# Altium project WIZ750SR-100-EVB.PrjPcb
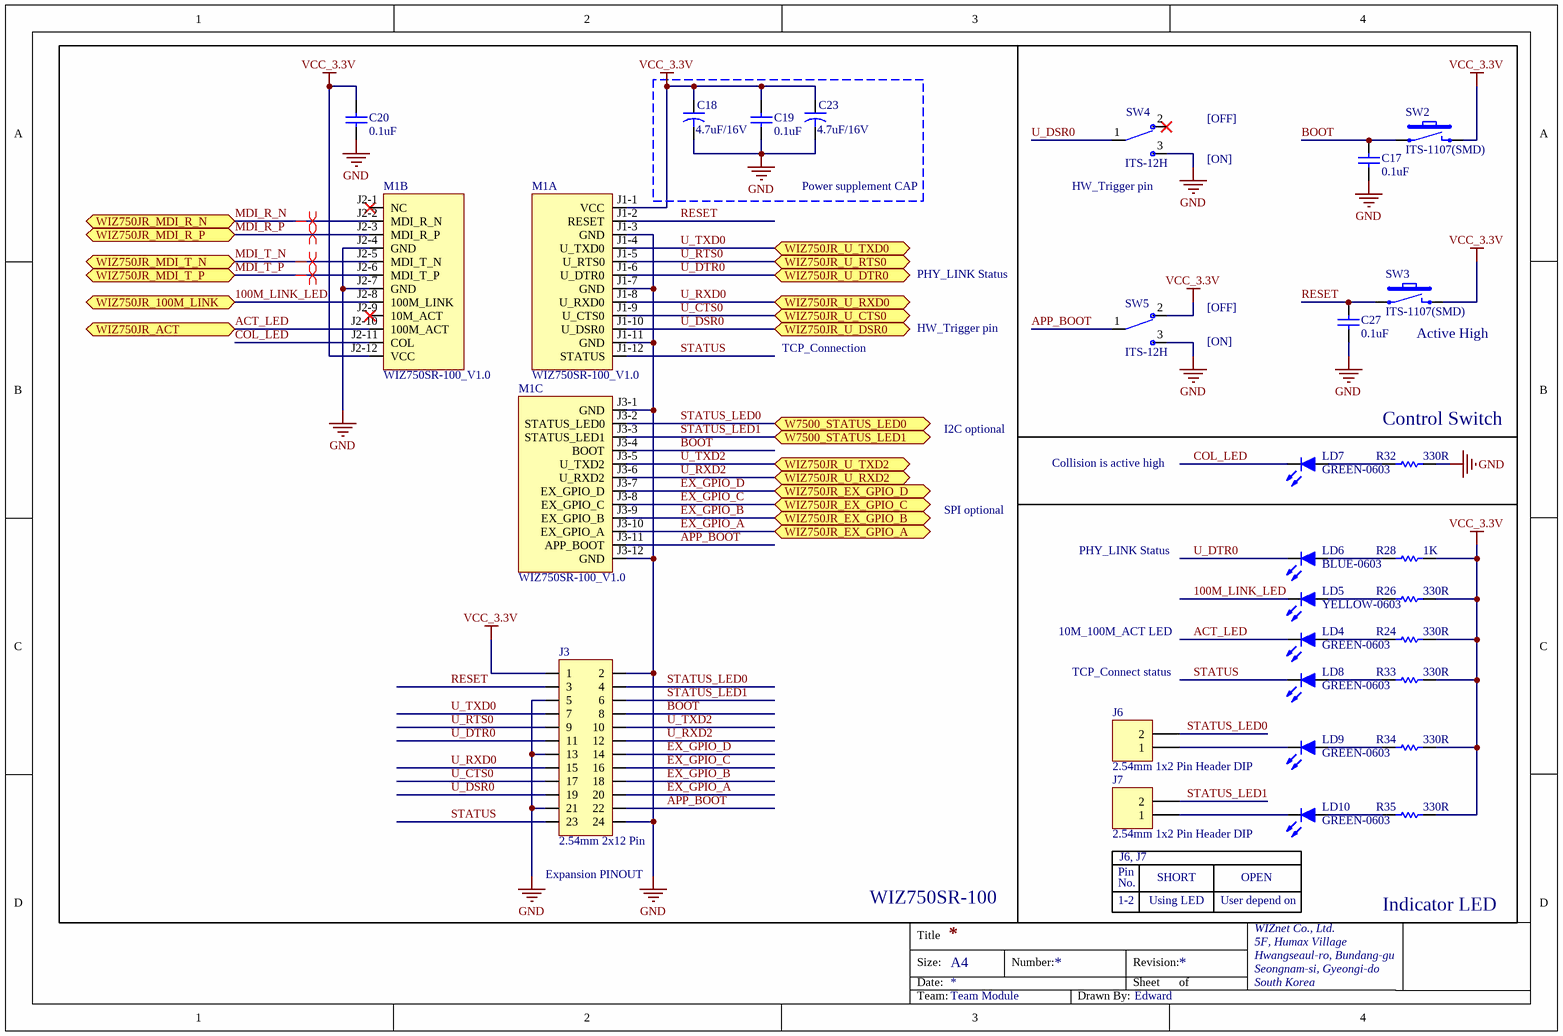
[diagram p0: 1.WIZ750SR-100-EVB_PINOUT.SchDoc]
4 sheets, 94 parts. Net scope: flat (ports and power ports of the same name join across sheets).
Board file: WIZ750SR-100-EVB.PcbDoc
Sheets:
  1.WIZ750SR-100-EVB_PINOUT.SchDoc
  2.WIZ750SR-100-EVB_PWR.SchDoc
  3.WIZ750SR-100-EVB_Data.SchDoc
  4.WIZ750SR-100-EVB_GPIO.SchDoc

## Sheet 1.WIZ750SR-100-EVB_PINOUT.SchDoc
size A4; Team: Wiki

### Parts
C17  0.1uF  [CAP-0603]
C18  4.7uF/16V  [CAP-A Size]
C19  0.1uF  [CAP-0603]
C20  0.1uF  [CAP-0603]
C23  4.7uF/16V  [CAP-A Size]
C27  0.1uF  [CAP-0603]
J3  2.54mm 2x12 Pin  [IDC-2x12_socket_2.54mm]
J6  2.54mm 1x2 Pin Header DIP  [IDC-1X2]
J7  2.54mm 1x2 Pin Header DIP  [IDC-1X2]
LD4  GREEN-0603  [LED-0603-GREEN]
LD5  YELLOW-0603  [LED-0603-YELLOW]
LD6  BLUE-0603  [LED-0603-GREEN]
LD7  GREEN-0603  [LED-0603-GREEN]
LD8  GREEN-0603  [LED-0603-GREEN]
LD9  GREEN-0603  [LED-0603-GREEN]
LD10  GREEN-0603  [LED-0603-GREEN]
M1  WIZ750SR-100_V1.0  [WIZ750JR_V1.0]  (parts A,B,C of 3)
R24  330R  [RES-0603]
R26  330R  [RES-0603]
R28  1K  [RES-0603]
R32  330R  [RES-0603]
R33  330R  [RES-0603]
R34  330R  [RES-0603]
R35  330R  [RES-0603]
SW2  ITS-1107(SMD)  [ITS-1107(SMD)]
SW3  ITS-1107(SMD)  [ITS-1107(SMD)]
SW4  ITS-12H  [ITS-12H]
SW5  ITS-12H  [ITS-12H]

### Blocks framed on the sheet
Power supplement CAP: C18 C19 C23

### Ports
W7500_STATUS_LED0, W7500_STATUS_LED1, WIZ750JR_100M_LINK, WIZ750JR_ACT, WIZ750JR_EX_GPIO_A, WIZ750JR_EX_GPIO_B, WIZ750JR_EX_GPIO_C, WIZ750JR_EX_GPIO_D, WIZ750JR_MDI_R_N, WIZ750JR_MDI_R_P, WIZ750JR_MDI_T_N, WIZ750JR_MDI_T_P, WIZ750JR_U_CTS0, WIZ750JR_U_DSR0, WIZ750JR_U_DTR0, WIZ750JR_U_RTS0, WIZ750JR_U_RXD0, WIZ750JR_U_RXD2, WIZ750JR_U_TXD0, WIZ750JR_U_TXD2

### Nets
GND: C17.1 C18.2 C19.1 C20.1 C23.2 C27.1 J3.2 J3.5 J3.13 J3.21 J3.24 M1.J1-3(GND) M1.J1-7(GND) M1.J1-11(GND) M1.J2-4(GND) M1.J2-7(GND) M1.J3-1(GND) M1.J3-12(GND) R32.2 SW4.3 SW5.3
VCC_3.3V: C18.1 C19.2 C20.2 C23.1 J3.1 M1.J1-1(VCC) M1.J2-12(VCC) R24.2 R26.2 R28.2 R33.2 R34.2 R35.2 SW2.2 SW3.2 SW5.2
100M_LINK_LED: LD5.2(K) M1.J2-8(100M_LINK) ; port WIZ750JR_100M_LINK
ACT_LED: LD4.2(K) M1.J2-10(100M_ACT) ; port WIZ750JR_ACT
APP_BOOT: J3.22 M1.J3-11(APP_BOOT) SW5.1
BOOT: C17.2 J3.8 M1.J3-4(BOOT) SW2.1
COL_LED: LD7.2(K) M1.J2-11(COL)
EX_GPIO_A: J3.20 M1.J3-10(EX_GPIO_A) ; port WIZ750JR_EX_GPIO_A
EX_GPIO_B: J3.18 M1.J3-9(EX_GPIO_B) ; port WIZ750JR_EX_GPIO_B
EX_GPIO_C: J3.16 M1.J3-8(EX_GPIO_C) ; port WIZ750JR_EX_GPIO_C
EX_GPIO_D: J3.14 M1.J3-7(EX_GPIO_D) ; port WIZ750JR_EX_GPIO_D
MDI_R_N: M1.J2-2(MDI_R_N) ; port WIZ750JR_MDI_R_N
MDI_R_P: M1.J2-3(MDI_R_P) ; port WIZ750JR_MDI_R_P
MDI_T_N: M1.J2-5(MDI_T_N) ; port WIZ750JR_MDI_T_N
MDI_T_P: M1.J2-6(MDI_T_P) ; port WIZ750JR_MDI_T_P
RESET: C27.2 J3.3 M1.J1-2(RESET) SW3.1
STATUS: J3.23 LD8.2(K) M1.J1-12(STATUS)
STATUS_LED0: J3.4 J6.2 M1.J3-2(STATUS_LED0) ; port W7500_STATUS_LED0
STATUS_LED1: J3.6 J7.2 M1.J3-3(STATUS_LED1) ; port W7500_STATUS_LED1
U_CTS0: J3.17 M1.J1-9(U_CTS0) ; port WIZ750JR_U_CTS0
U_DSR0: J3.19 M1.J1-10(U_DSR0) SW4.1 ; port WIZ750JR_U_DSR0
U_DTR0: J3.11 LD6.2(K) M1.J1-6(U_DTR0) ; port WIZ750JR_U_DTR0
U_RTS0: J3.9 M1.J1-5(U_RTS0) ; port WIZ750JR_U_RTS0
U_RXD0: J3.15 M1.J1-8(U_RXD0) ; port WIZ750JR_U_RXD0
U_RXD2: J3.12 M1.J3-6(U_RXD2) ; port WIZ750JR_U_RXD2
U_TXD0: J3.7 M1.J1-4(U_TXD0) ; port WIZ750JR_U_TXD0
U_TXD2: J3.10 M1.J3-5(U_TXD2) ; port WIZ750JR_U_TXD2
NetJ6_1: J6.1 LD9.2(K)
NetJ7_1: J7.1 LD10.2(K)
NetLD4_1: LD4.1(A) R24.1
NetLD5_1: LD5.1(A) R26.1
NetLD6_1: LD6.1(A) R28.1
NetLD7_1: LD7.1(A) R32.1
NetLD8_1: LD8.1(A) R33.1
NetLD9_1: LD9.1(A) R34.1
NetLD10_1: LD10.1(A) R35.1

Not connected (* = marked no-connect by the designer): M1 J2-1(NC)* J2-9(10M_ACT)*; SW4 2*

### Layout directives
differential pair: MDI_R_N, MDI_R_P, MDI_T_N, MDI_T_P

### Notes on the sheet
- [ON]
- [OFF]
- (near SW4) HW_Trigger pin
- PHY_LINK Status
- TCP_Connection
- HW_Trigger pin
- (near SW3) Active High
- I2C optional
- (near R32) Control Switch
- SPI optional
- Collision is active high
- 10M_100M_ACT LED
- TCP_Connect status
- (near J3) Expansion PINOUT
- WIZ750SR-100
- Pin
- 1-2
- No.
- (near J7) J6, J7
- Using LED
- SHORT
- User depend on
- OPEN
- Indicator LED

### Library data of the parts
C17 C19 C20 C27 = CAP-0603: Ceramic CAP 0603(1608)
C18 C23 = CAP-A Size: Tantla CAP A Size EIA/IECQ 3216
J3 = Header 2x12: pin header 2.54mm 2x12
J6 J7 = Header 1x2: pin header 2.54mm 1x2
LD4-LD10 = LED-0603
M1 = WIZ750JR_V0.2: Serial to ethernet module, 50mmx30mm, 7500 + External PHY
R24 R26 R28 R32-R35 = RES-0603
SW2 SW3 = ITS-1107(SMD): TACT SW, SMD
SW4 SW5 = ITS-12H: Slide Switch

## Sheet 2.WIZ750SR-100-EVB_PWR.SchDoc
size A4; Team: Wiki
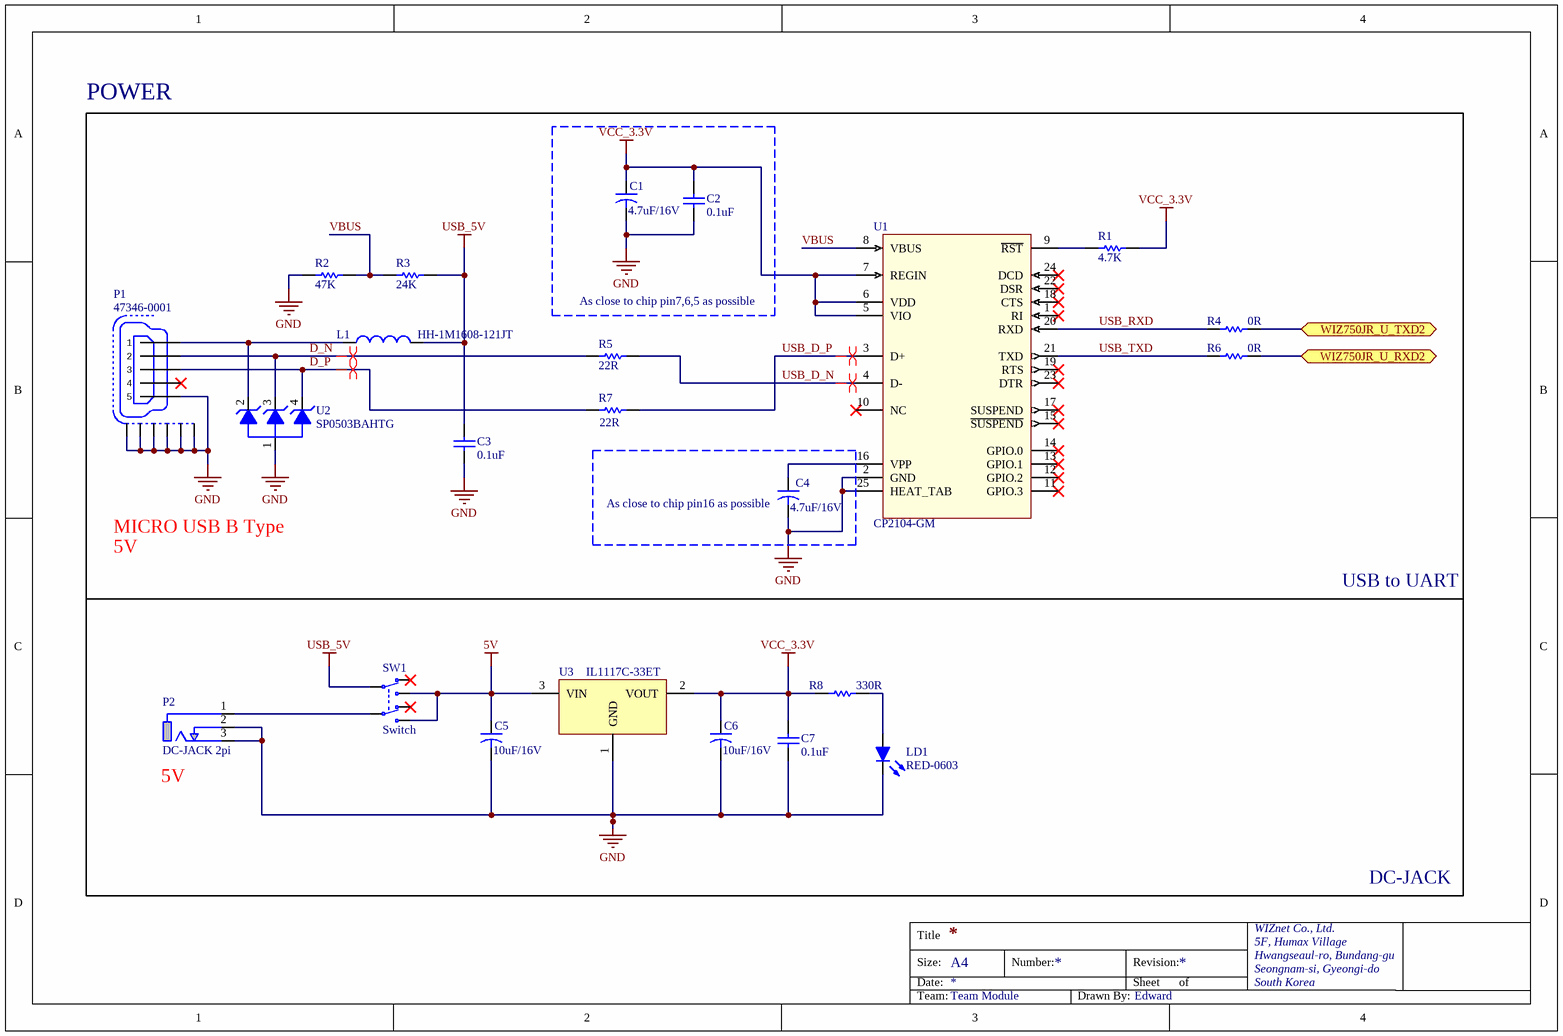
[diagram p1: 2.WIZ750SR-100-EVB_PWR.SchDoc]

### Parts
C1  4.7uF/16V  [CAP-A Size]
C2  0.1uF  [CAP-0603]
C3  0.1uF  [CAP-0603]
C4  4.7uF/16V  [CAP-A Size]
C5  10uF/16V  [CAP-A Size]
C6  10uF/16V  [CAP-A Size]
C7  0.1uF  [CAP-0603]
L1  HH-1M1608-121JT  [IND-0603]
LD1  RED-0603  [LED-0603-RED]
P1  47346-0001  [USB-MICRO-B(SMD)]
P2  DC-JACK 2pi  [DC-JACK 2pi]
R1  4.7K  [RES-0603]
R2  47K  [RES-0603]
R3  24K  [RES-0603]
R4  0R  [RES-0603]
R5  22R  [RES-0603]
R6  0R  [RES-0603]
R7  22R  [RES-0603]
R8  330R  [RES-0603]
SW1  Switch  [JS202011SCQN]
U1  CP2104-GM  [CP2104_QFN24_PAD]
U2  SP0503BAHTG  [SP0503BAHTG]
U3  IL1117C-33ET  [IL1117C-33ET]

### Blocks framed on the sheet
POWER: C3 C5-C7 L1 LD1 P1 P2 R1-R8 SW1 U1-U3
As close to chip pin7,6,5 as possible: C1 C2
As close to chip pin16 as possible: C4

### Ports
WIZ750JR_U_RXD2, WIZ750JR_U_TXD2

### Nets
5V: C5.1 SW1.1(N.O-1) SW1.4(N.O-2) U3.3(VIN)
GND: C1.2 C2.1 C3.1 C4.2 C5.2 C6.2 C7.1 LD1.2(K) P1.5 P1.6 P1.7 P1.8 P1.9 P1.10 P1.11 P2.2(GND) P2.3(GND) R2.1 U1.2(GND) U1.25(HEAT_TAB) U2.1 U3.1(GND)
USB_5V: C3.2 L1.2 R3.2 SW1.2(COM-1)
VCC_3.3V: C1.1 C2.2 C6.1 C7.2 R1.2 R8.1 U1.5(VIO) U1.6(VDD) U1.7(REGIN) U3.2(VOUT)
D_N: P1.2 R5.1 U2.3
D_P: P1.3 R7.1 U2.4
U_RXD2: R6.2 ; port WIZ750JR_U_RXD2
U_TXD2: R4.2 ; port WIZ750JR_U_TXD2
USB_D_N: R5.2 U1.4(D-)
USB_D_P: R7.2 U1.3(D+)
USB_RXD: R4.1 U1.20(RXD)
USB_TXD: R6.1 U1.21(TXD)
VBUS: R2.2 R3.1 U1.8(VBUS)
NetC4_1: C4.1 U1.16(VPP)
NetL1_1: L1.1 P1.1 U2.2
NetLD1_1: LD1.1(A) R8.2
NetP2_1: P2.1(VCC) SW1.5(COM-2)
NetR1_1: R1.1 U1.9(~{RST})

Not connected (* = marked no-connect by the designer): P1 4*; SW1 3(N.C-1)* 6(N.C-2)*; U1 1(RI)* 10(NC)* 11(GPIO.3)* 12(GPIO.2)* 13(GPIO.1)* 14(GPIO.0)* 15(~{SUSPEND})* 17(SUSPEND)* 18(CTS)* 19(RTS)* 22(DSR)* 23(DTR)* 24(DCD)*

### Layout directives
differential pair: D_N, D_P, USB_D_N, USB_D_P

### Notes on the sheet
- MICRO USB B Type
- 5V
- USB to UART
- (near P2) 5V
- DC-JACK

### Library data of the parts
C1 C4-C6 = CAP-A Size: Tantla CAP A Size EIA/IECQ 3216
C2 C3 C7 = CAP-0603: Ceramic CAP 0603(1608)
L1 = IND-0603: Inductor 0603(1608)
LD1 = LED-0603
P1 = 47346-0001: MICRO USB B Type
R1-R8 = RES-0603
SW1 = SW-DPDT: SMD slide Switch (ON-ON); Manufacturer: C&K Components; 2nd source part number: 232-0019; Artikkelnr Noca: N.A.
U1 = CP2104-GM: USB to UART Bridge, SiliconLabs
U2 = SP0503BAHTG: Little Fuse, Silicon Protection Array Products
U3 = IL1117C-33ET: 1A, 3.3V

## Sheet 3.WIZ750SR-100-EVB_Data.SchDoc
size A4; Team: Wiki
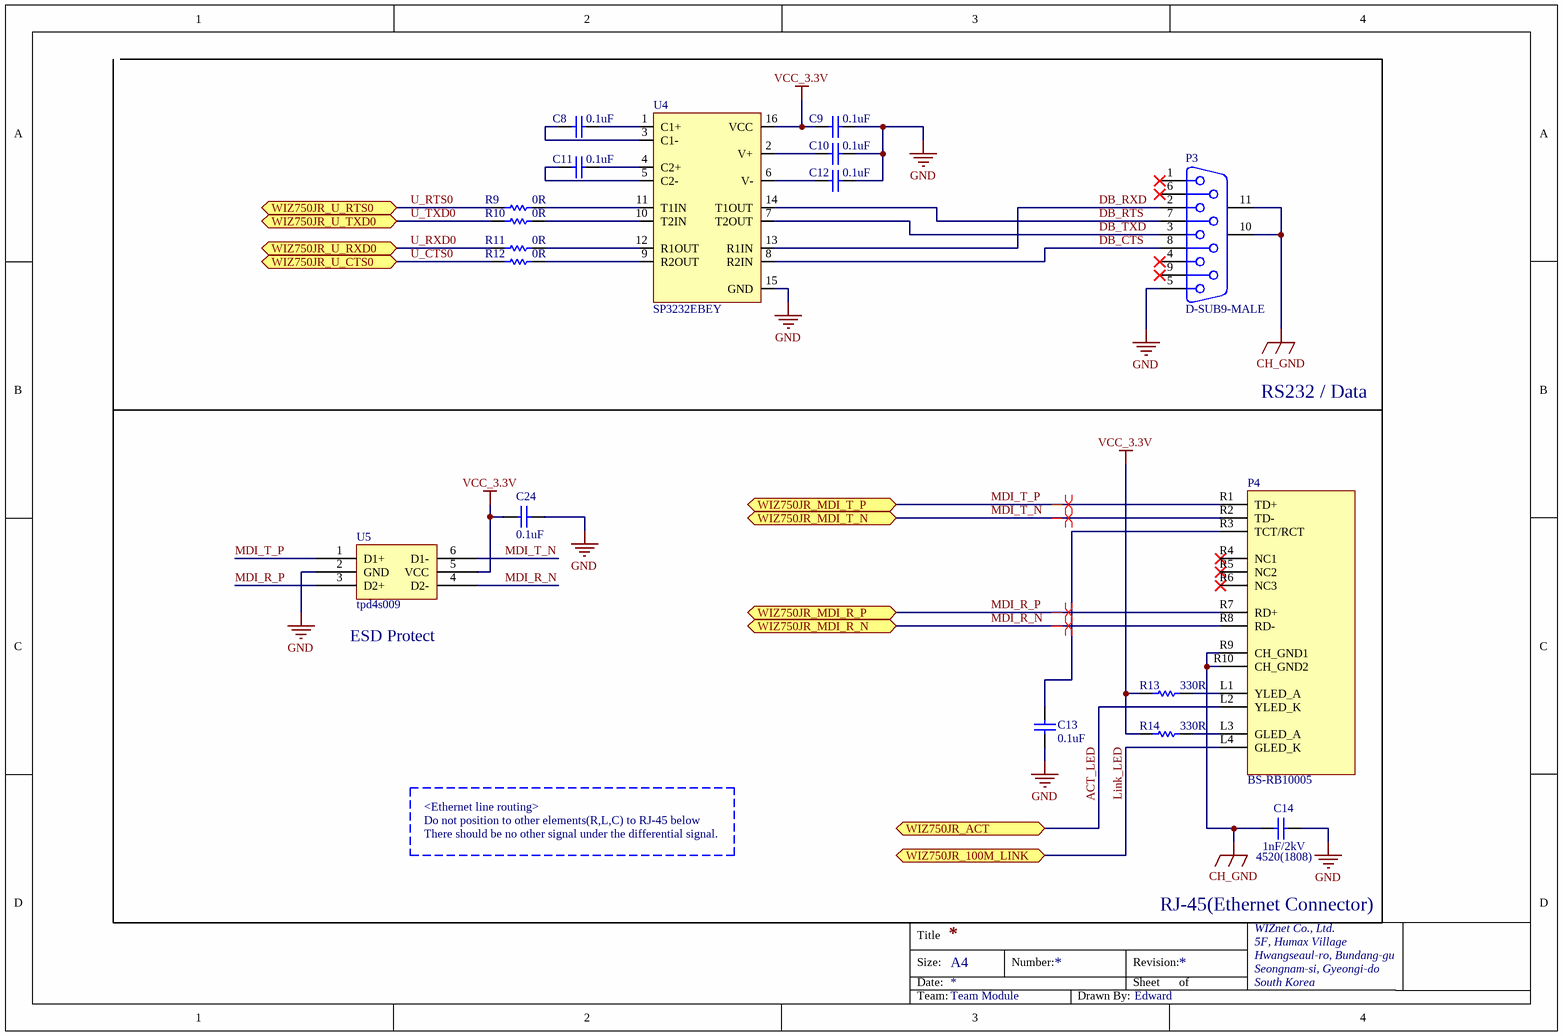
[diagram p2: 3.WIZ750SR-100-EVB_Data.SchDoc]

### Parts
C8  0.1uF  [CAP-0603]
C9  0.1uF  [CAP-0603]
C10  0.1uF  [CAP-0603]
C11  0.1uF  [CAP-0603]
C12  0.1uF  [CAP-0603]
C13  0.1uF  [CAP-0603]
C14  1nF/2kV  [CAP-1808]
C24  0.1uF  [CAP-0603]
P3  D-SUB9-MALE  [D-SUB9-MALE]
P4  BS-RB10005  [RJ45-125BAG1A]
R9  0R  [RES-0603]
R10  0R  [RES-0603]
R11  0R  [RES-0603]
R12  0R  [RES-0603]
R13  330R  [RES-0603]
R14  330R  [RES-0603]
U4  SP3232EBEY  [SP3232EBEY-TSSOP16]
U5  tpd4s009  [SOT-23-6L]

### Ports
WIZ750JR_100M_LINK, WIZ750JR_ACT, WIZ750JR_MDI_R_N, WIZ750JR_MDI_R_P, WIZ750JR_MDI_T_N, WIZ750JR_MDI_T_P, WIZ750JR_U_CTS0, WIZ750JR_U_RTS0, WIZ750JR_U_RXD0, WIZ750JR_U_TXD0

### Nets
CH_GND: C14.2 P3.10(MH1) P3.11(MH2) P4.R9(CH_GND1) P4.R10(CH_GND2)
GND: C9.1 C10.1 C12.1 C13.1 C14.1 C24.2 P3.5 U4.15(GND) U5.2(GND)
VCC_3.3V: C9.2 C24.1 R13.1 R14.1 U4.16(VCC) U5.5(VCC)
ACT_LED: P4.L2(YLED_K) ; port WIZ750JR_ACT
DB_CTS: P3.8 U4.8(R2IN)
DB_RTS: P3.7 U4.14(T1OUT)
DB_RXD: P3.2 U4.13(R1IN)
DB_TXD: P3.3 U4.7(T2OUT)
Link_LED: P4.L4(GLED_K) ; port WIZ750JR_100M_LINK  [project net 100M_LINK_LED]
MDI_R_N: P4.R8(RD-) U5.4(D2-) ; port WIZ750JR_MDI_R_N
MDI_R_P: P4.R7(RD+) U5.3(D2+) ; port WIZ750JR_MDI_R_P
MDI_T_N: P4.R2(TD-) U5.6(D1-) ; port WIZ750JR_MDI_T_N
MDI_T_P: P4.R1(TD+) U5.1(D1+) ; port WIZ750JR_MDI_T_P
U_CTS0: R12.1 ; port WIZ750JR_U_CTS0
U_RTS0: R9.1 ; port WIZ750JR_U_RTS0
U_RXD0: R11.1 ; port WIZ750JR_U_RXD0
U_TXD0: R10.1 ; port WIZ750JR_U_TXD0
NetC8_1: C8.1 U4.1(C1+)
NetC8_2: C8.2 U4.3(C1-)
NetC10_2: C10.2 U4.2(V+)
NetC11_1: C11.1 U4.4(C2+)
NetC11_2: C11.2 U4.5(C2-)
NetC12_2: C12.2 U4.6(V-)
NetC13_2: C13.2 P4.R3(TCT/RCT)
NetP4_L1: P4.L1(YLED_A) R13.2
NetP4_L3: P4.L3(GLED_A) R14.2
NetR9_2: R9.2 U4.11(T1IN)
NetR10_2: R10.2 U4.10(T2IN)
NetR11_2: R11.2 U4.12(R1OUT)
NetR12_2: R12.2 U4.9(R2OUT)

Not connected (* = marked no-connect by the designer): P3 1* 4* 6* 9*; P4 R4(NC1)* R5(NC2)* R6(NC3)*

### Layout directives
differential pair: MDI_R_N, MDI_R_P, MDI_T_N, MDI_T_P

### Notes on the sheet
- RS232 / Data
- (near U5) ESD Protect
- <Ethernet line routing>
- Do not position to other elements(R,L,C) to RJ-45 below
- There should be no other signal under the differential signal.
- RJ-45(Ethernet Connector)
- (near C14) 4520(1808)

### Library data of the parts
C8-C13 C24 = CAP-0603: Ceramic CAP 0603(1608)
C14 = CAP-1808: Ceramic CAP 1808(4520)
P3 = D-SUB9-MALE: D-SUB-9, MALE,  Right Angle; PackageDocument: O; Positions: 9; Gender: Receptacle
P4 = RB1-125BAG1A: 10/100 BASE-TX MAGJACK
R9-R14 = RES-0603
U4 = SP3232EBEY: True +3.0V to +5.5V RS-232 Transceivers TSSOP16
U5 = tpd4s009: 6-PIN SOT DBVor DCK Package

## Sheet 4.WIZ750SR-100-EVB_GPIO.SchDoc
size A4; Team: Wiki
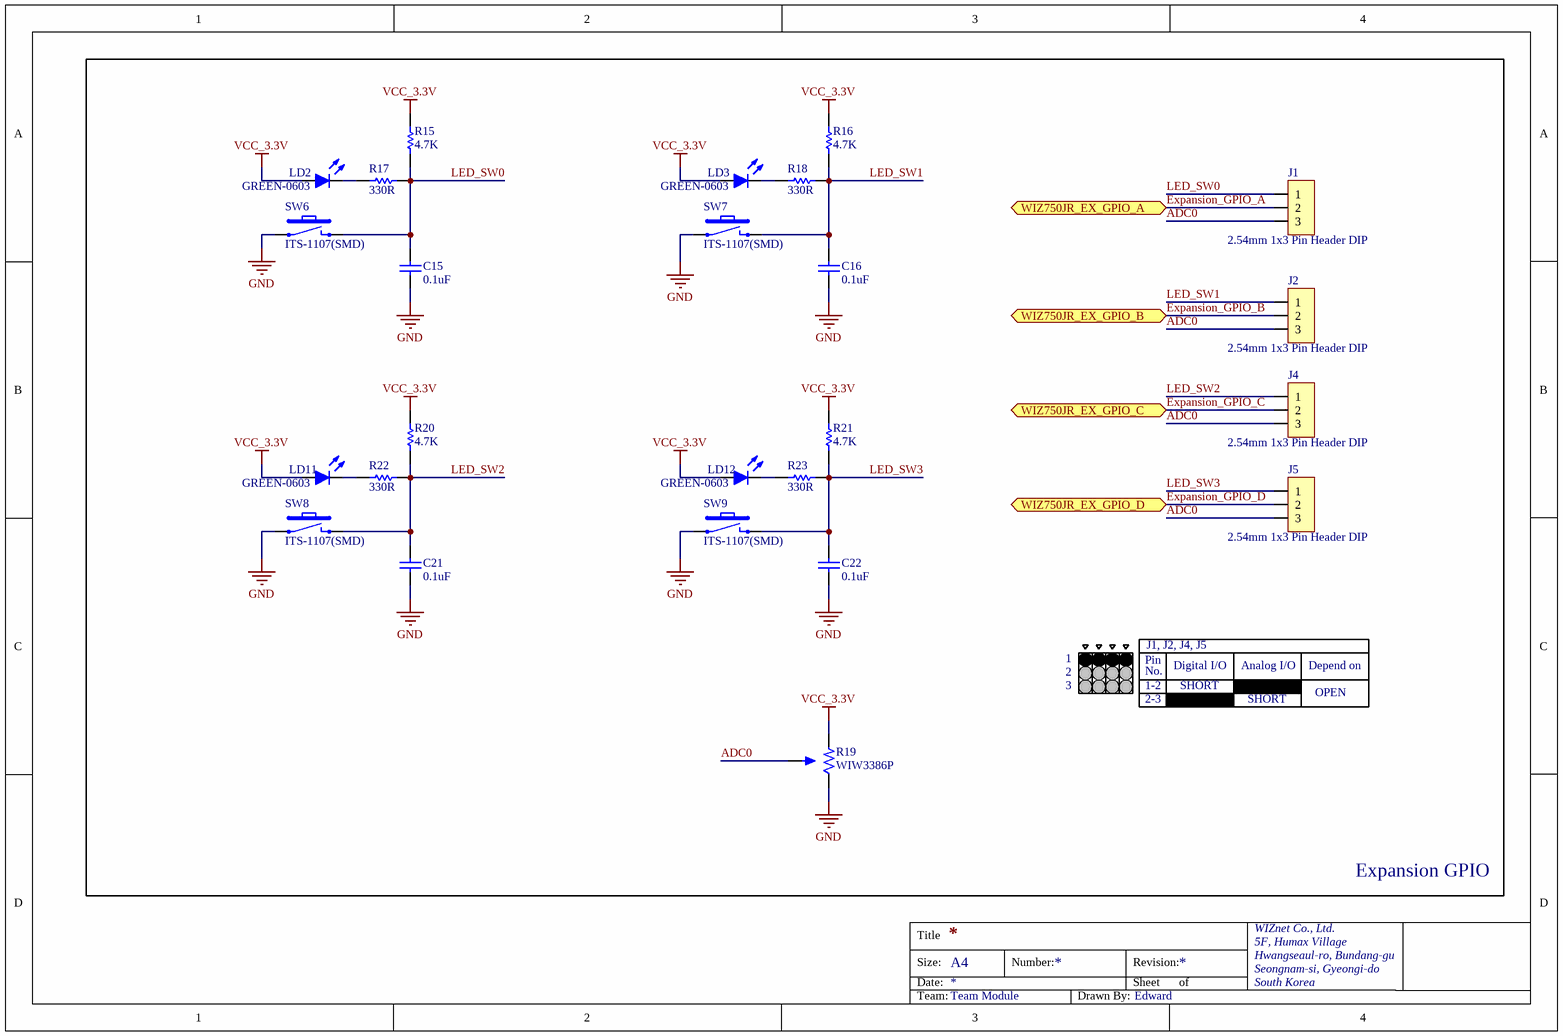
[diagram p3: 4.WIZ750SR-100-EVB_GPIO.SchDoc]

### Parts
C15  0.1uF  [CAP-0603]
C16  0.1uF  [CAP-0603]
C21  0.1uF  [CAP-0603]
C22  0.1uF  [CAP-0603]
J1  2.54mm 1x3 Pin Header DIP  [IDC-1X3]
J2  2.54mm 1x3 Pin Header DIP  [IDC-1X3]
J4  2.54mm 1x3 Pin Header DIP  [IDC-1X3]
J5  2.54mm 1x3 Pin Header DIP  [IDC-1X3]
LD2  GREEN-0603  [LED-0603-GREEN]
LD3  GREEN-0603  [LED-0603-GREEN]
LD11  GREEN-0603  [LED-0603-GREEN]
LD12  GREEN-0603  [LED-0603-GREEN]
R15  4.7K  [RES-0603]
R16  4.7K  [RES-0603]
R17  330R  [RES-0603]
R18  330R  [RES-0603]
R19  WIW3386P  [WIW3386P]
R20  4.7K  [RES-0603]
R21  4.7K  [RES-0603]
R22  330R  [RES-0603]
R23  330R  [RES-0603]
SW6  ITS-1107(SMD)  [ITS-1107(SMD)]
SW7  ITS-1107(SMD)  [ITS-1107(SMD)]
SW8  ITS-1107(SMD)  [ITS-1107(SMD)]
SW9  ITS-1107(SMD)  [ITS-1107(SMD)]

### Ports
WIZ750JR_EX_GPIO_A, WIZ750JR_EX_GPIO_B, WIZ750JR_EX_GPIO_C, WIZ750JR_EX_GPIO_D

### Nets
GND: C15.1 C16.1 C21.1 C22.1 R19.3 SW6.1 SW7.1 SW8.1 SW9.1
VCC_3.3V: LD2.1(A) LD3.1(A) LD11.1(A) LD12.1(A) R15.2 R16.2 R19.1 R20.2 R21.2
ADC0: J1.3 J2.3 J4.3 J5.3 R19.2
Expansion_GPIO_A: J1.2 ; port WIZ750JR_EX_GPIO_A  [project net EX_GPIO_A]
Expansion_GPIO_B: J2.2 ; port WIZ750JR_EX_GPIO_B  [project net EX_GPIO_B]
Expansion_GPIO_C: J4.2 ; port WIZ750JR_EX_GPIO_C  [project net EX_GPIO_C]
Expansion_GPIO_D: J5.2 ; port WIZ750JR_EX_GPIO_D  [project net EX_GPIO_D]
LED_SW0: C15.2 J1.1 R15.1 R17.2 SW6.2
LED_SW1: C16.2 J2.1 R16.1 R18.2 SW7.2
LED_SW2: C21.2 J4.1 R20.1 R22.2 SW8.2
LED_SW3: C22.2 J5.1 R21.1 R23.2 SW9.2
NetLD2_2: LD2.2(K) R17.1
NetLD3_2: LD3.2(K) R18.1
NetLD11_2: LD11.2(K) R22.1
NetLD12_2: LD12.2(K) R23.1

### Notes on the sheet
- J1, J2, J4, J5
- 3
- 2
- 1
- Pin
- 1-2
- 2-3
- No.
- Digital I/O
- SHORT
- Analog I/O
- Depend on
- OPEN
- Expansion GPIO

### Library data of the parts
C15 C16 C21 C22 = CAP-0603: Ceramic CAP 0603(1608)
LD2 LD3 LD11 LD12 = LED-0603
R15-R18 R20-R23 = RES-0603
R19 = WIW3386P: Potentiometer
SW6-SW9 = ITS-1107(SMD): TACT SW, SMD

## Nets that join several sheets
GND: 1.WIZ750SR-100-EVB_PINOUT (21 pins), 2.WIZ750SR-100-EVB_PWR (22 pins), 3.WIZ750SR-100-EVB_Data (9 pins), 4.WIZ750SR-100-EVB_GPIO (9 pins)
VCC_3.3V: 1.WIZ750SR-100-EVB_PINOUT (16 pins), 2.WIZ750SR-100-EVB_PWR (10 pins), 3.WIZ750SR-100-EVB_Data (6 pins), 4.WIZ750SR-100-EVB_GPIO (9 pins)
100M_LINK_LED: 1.WIZ750SR-100-EVB_PINOUT (LD5.2 M1.J2-8), 3.WIZ750SR-100-EVB_Data (P4.L4)
ACT_LED: 1.WIZ750SR-100-EVB_PINOUT (LD4.2 M1.J2-10), 3.WIZ750SR-100-EVB_Data (P4.L2)
EX_GPIO_A: 1.WIZ750SR-100-EVB_PINOUT (J3.20 M1.J3-10), 4.WIZ750SR-100-EVB_GPIO (J1.2)
EX_GPIO_B: 1.WIZ750SR-100-EVB_PINOUT (J3.18 M1.J3-9), 4.WIZ750SR-100-EVB_GPIO (J2.2)
EX_GPIO_C: 1.WIZ750SR-100-EVB_PINOUT (J3.16 M1.J3-8), 4.WIZ750SR-100-EVB_GPIO (J4.2)
EX_GPIO_D: 1.WIZ750SR-100-EVB_PINOUT (J3.14 M1.J3-7), 4.WIZ750SR-100-EVB_GPIO (J5.2)
MDI_R_N: 1.WIZ750SR-100-EVB_PINOUT (M1.J2-2), 3.WIZ750SR-100-EVB_Data (P4.R8 U5.4)
MDI_R_P: 1.WIZ750SR-100-EVB_PINOUT (M1.J2-3), 3.WIZ750SR-100-EVB_Data (P4.R7 U5.3)
MDI_T_N: 1.WIZ750SR-100-EVB_PINOUT (M1.J2-5), 3.WIZ750SR-100-EVB_Data (P4.R2 U5.6)
MDI_T_P: 1.WIZ750SR-100-EVB_PINOUT (M1.J2-6), 3.WIZ750SR-100-EVB_Data (P4.R1 U5.1)
U_CTS0: 1.WIZ750SR-100-EVB_PINOUT (J3.17 M1.J1-9), 3.WIZ750SR-100-EVB_Data (R12.1)
U_RTS0: 1.WIZ750SR-100-EVB_PINOUT (J3.9 M1.J1-5), 3.WIZ750SR-100-EVB_Data (R9.1)
U_RXD0: 1.WIZ750SR-100-EVB_PINOUT (J3.15 M1.J1-8), 3.WIZ750SR-100-EVB_Data (R11.1)
U_RXD2: 1.WIZ750SR-100-EVB_PINOUT (J3.12 M1.J3-6), 2.WIZ750SR-100-EVB_PWR (R6.2)
U_TXD0: 1.WIZ750SR-100-EVB_PINOUT (J3.7 M1.J1-4), 3.WIZ750SR-100-EVB_Data (R10.1)
U_TXD2: 1.WIZ750SR-100-EVB_PINOUT (J3.10 M1.J3-5), 2.WIZ750SR-100-EVB_PWR (R4.2)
